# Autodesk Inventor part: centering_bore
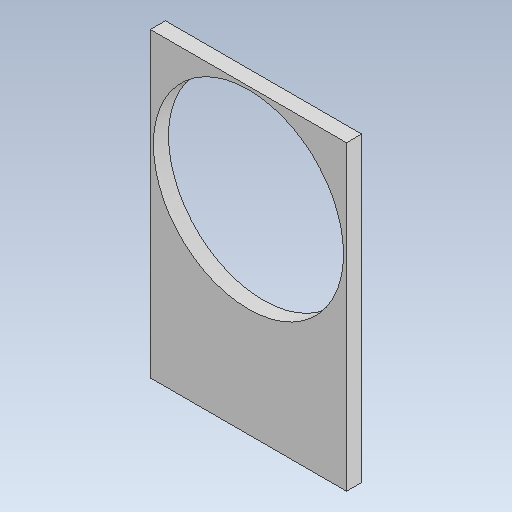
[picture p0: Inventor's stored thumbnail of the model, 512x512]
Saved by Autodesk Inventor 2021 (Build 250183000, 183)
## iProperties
Created: 2026-10
Part Number: centering_bore
Material: Generic
Document SubType Name: Modeling
Designer: alolo
Density: 1 g/cm^3
Appearance: Default
Author: alolo
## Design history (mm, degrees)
sketch "Sketch1"
  geometry: L1 (-32.5, 32.5)-(32.5, 32.5); L2 (32.5, 32.5)-(32.5, -67.5); L3 (32.5, -67.5)-(-32.5, -67.5); L4 (-32.5, -67.5)-(-32.5, 32.5); C1 r 31.5 at (0, 0); 3 further points
  constraints: 8 end point, 2 midpoint, 1 centre point, 1 coincident, 1 horizontal, 1 parallel, 1 perpendicular, 1 vertical alignment
  dimensions: "d0" = 63 diameter of C1; "d4" = 65 distance of L1.start L1.end (= slide_width); "d5" = 100 distance of L1.end L2.end
extrude "Extrusion1" new body sketch "Sketch1" distance "d2" = 5 (= wood_thickness); taper "d3" = 0 deg
body "Solid1"
other parameters: "slide_length" = 195 [user parameter], "slide_angle" = 7 deg [user parameter], "slide_width" = 65 [user parameter; used in 1 equation term], "wood_thickness" = 5 [user parameter; used in 1 equation term], "aclyric_thickness" = 6 [user parameter]
